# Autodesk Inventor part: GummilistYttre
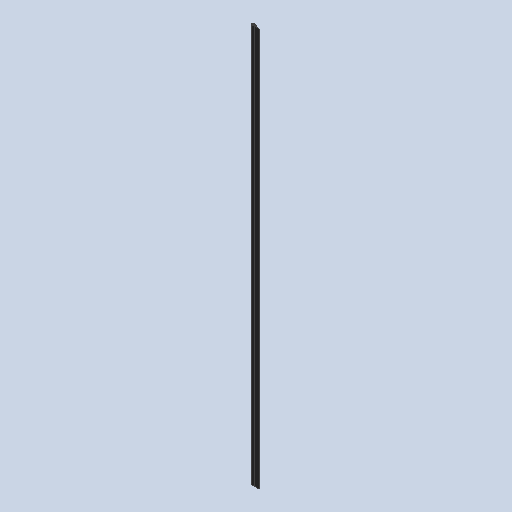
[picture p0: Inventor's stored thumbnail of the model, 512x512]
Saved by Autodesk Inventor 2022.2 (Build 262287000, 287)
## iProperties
Created: 2019-06
Part Number: GummilistYttre
Material: Rubber
Document SubType Name: Modeling
Designer: cl
Density: 0.93 g/cm^3
Appearance: Rubber - Black
Author: cl
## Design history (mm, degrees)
sketch "Sketch1"
  geometry: L1 (0, 0)-(28, 0); L2 (33, -5)-(33, -15); L3 (28, -20)-(0, -20); L4 (0, 0)-(-50, 0); L5 (-50, 0)-(-50, -0.01); L6 (-50, -0.01)-(0, -0.01); L7 (0, -0.01)-(0, -20); A1 r 5 centre (28, -5) between (33, -5) and (28, 0); A2 r 5 centre (28, -15) between (28, -20) and (33, -15); 2 further points
  constraints: 14 end point, 4 point on circle, 4 point on line, 4 tangent, 3 perpendicular, 2 centre point, 2 horizontal, 2 parallel, 1 equal radius
  dimensions: "d0" = 33 distance of point (33, -20) L3.end; "d1" = 20 distance of point (33, 0) point (33, -20); "d2" = 5 radius of A1; "d5" = 50 distance of L1.start L4.end; "d6" = 0.01 distance of L4.end L5.end; "d7" = 50 distance of L5.end L6.end
extrude "Extrusion1" new body sketch "Sketch1" distance "d3" = 4005 (computed from Daghöjd_1); taper "d4" = 0 deg
body "Solid1"
other parameters: "BladBredd" = 987.5, "Fönsterhöjd" = 862
